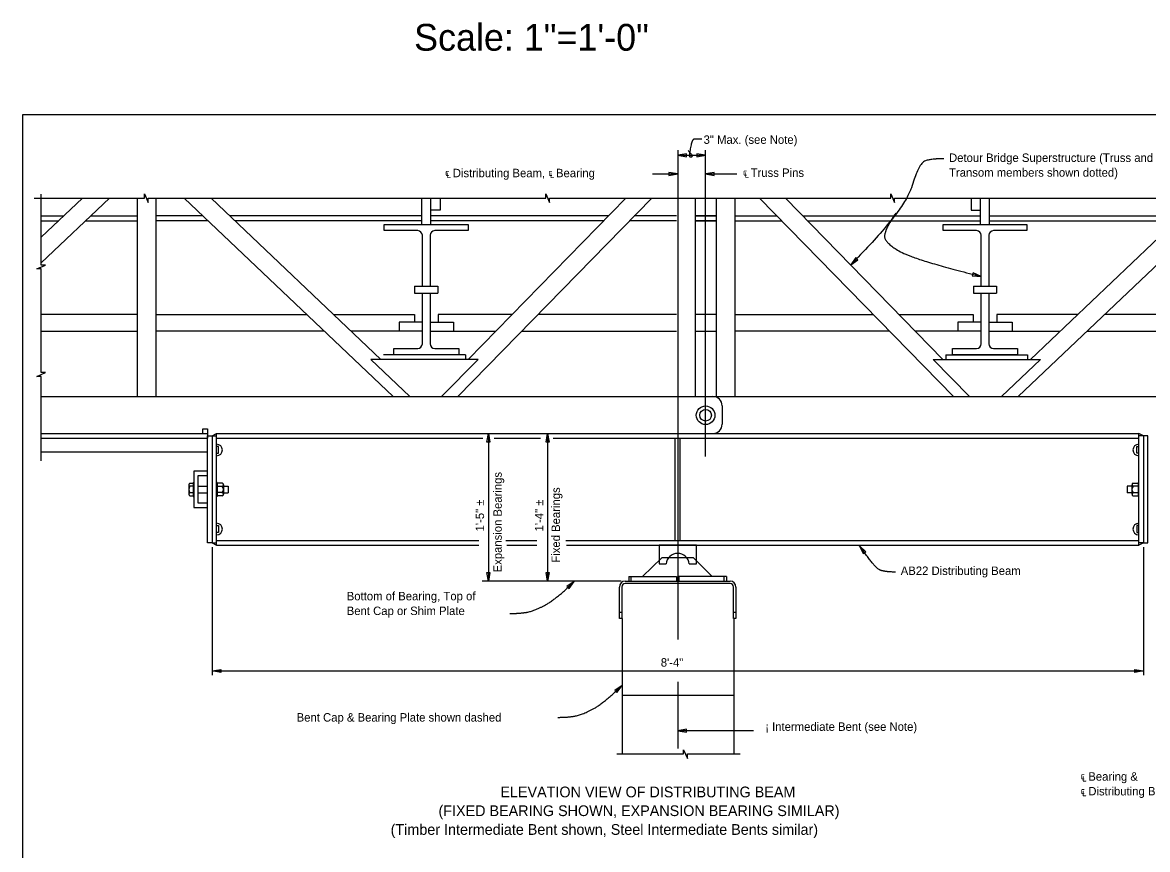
# Model space of a CAD drawing. Extents: x 112363.6 to 112390.2, y 109543.2 to 109558.
# Drawn here: x 112363.65 to 112373.71, y 109550.57 to 109557.97 of the extents above; entities that cross this region are included whole.
import ezdxf

# ---------------------------------------------------------------- set-up
doc = ezdxf.new("R2010")
doc.units = 0
for name, color, linetype in [('ActivePts-ConstElements', 7, 'Continuous'), ('CL_Minor', 7, 'Continuous'), ('Dimension', 7, 'Continuous'), ('SteelMisc', 7, 'Continuous'), ('SteelMisc_h', 7, 'Continuous'), ('Symbols', 7, 'Continuous'), ('TextStructures', 7, 'Continuous'), ('Wood', 7, 'Continuous')]:
    doc.layers.add(name, color=color, linetype=linetype)

msp = doc.modelspace()

# ---------------------------------------------------------------- linework, layer by layer
at = {"layer": 'ActivePts-ConstElements'}
msp.add_lwpolyline([(112363.648, 109547.417), (112379.042, 109547.417), (112379.042, 109557.147), (112363.648, 109557.147)], close=True, dxfattribs=at)
at = {"layer": 'CL_Minor'}
for p, q in [((112369.51, 109556.831), (112369.51, 109552.449)), ((112369.76, 109554.089), (112369.76, 109556.831)), ((112369.51, 109552.072), (112369.51, 109551.473))]:
    msp.add_line(p, q, dxfattribs=at)
at = {"layer": 'Dimension'}
for p, q in [((112369.51, 109556.786), (112369.76, 109556.786)), ((112369.284, 109556.619), (112369.51, 109556.619)), ((112369.76, 109556.619), (112370.04, 109556.619)), ((112367.816, 109554.294), (112367.816, 109552.972)), ((112368.346, 109554.294), (112368.346, 109552.972)), ((112365.344, 109553.278), (112365.344, 109552.131)), ((112373.677, 109553.278), (112373.677, 109552.131)), ((112369.004, 109552.972), (112367.76, 109552.972)), ((112365.344, 109552.169), (112373.677, 109552.169))]:
    msp.add_line(p, q, dxfattribs=at)
for points in [[(112369.51, 109556.786), (112369.588, 109556.773), (112369.588, 109556.799)], [(112369.76, 109556.786), (112369.682, 109556.799), (112369.682, 109556.773)], [(112369.51, 109556.619), (112369.432, 109556.632), (112369.432, 109556.605)], [(112369.76, 109556.619), (112369.838, 109556.605), (112369.838, 109556.632)], [(112371.058, 109555.804), (112371.122, 109555.85), (112371.103, 109555.869)], [(112372.225, 109555.701), (112372.153, 109555.732), (112372.146, 109555.707)], [(112367.803, 109554.216), (112367.816, 109554.294), (112367.829, 109554.216)], [(112368.333, 109554.216), (112368.346, 109554.294), (112368.359, 109554.216)], [(112371.137, 109553.29), (112371.171, 109553.219), (112371.193, 109553.234)], [(112367.829, 109553.05), (112367.816, 109552.972), (112367.803, 109553.05)], [(112368.359, 109553.05), (112368.346, 109552.972), (112368.333, 109553.05)], [(112368.584, 109552.97), (112368.519, 109552.924), (112368.538, 109552.906)], [(112365.422, 109552.156), (112365.344, 109552.169), (112365.422, 109552.182)], [(112373.599, 109552.182), (112373.677, 109552.169), (112373.599, 109552.156)], [(112369.012, 109552.039), (112368.947, 109551.994), (112368.966, 109551.975)], [(112369.51, 109551.633), (112369.588, 109551.62), (112369.588, 109551.646)]]:
    msp.add_lwpolyline(points, close=True, dxfattribs=at)
for points in [[(112369.726, 109556.93), (112369.673, 109556.93), (112369.648, 109556.93), (112369.631, 109556.892), (112369.614, 109556.791), (112369.614, 109556.772), (112369.642, 109556.772), (112369.642, 109556.789), (112369.604, 109556.828)], [(112371.89, 109556.755), (112371.797, 109556.755), (112371.667, 109556.721), (112371.547, 109556.301), (112371.058, 109555.804)], [(112371.461, 109556.268), (112371.361, 109556.118), (112371.361, 109556.002), (112371.635, 109555.848), (112372.225, 109555.701)], [(112371.459, 109553.054), (112371.347, 109553.054), (112371.269, 109553.103), (112371.137, 109553.29)], [(112368.009, 109552.683), (112368.101, 109552.683), (112368.226, 109552.706), (112368.422, 109552.81), (112368.584, 109552.97)], [(112368.437, 109551.753), (112368.529, 109551.753), (112368.654, 109551.776), (112368.85, 109551.879), (112369.012, 109552.039)]]:
    msp.add_open_spline(points, degree=2, dxfattribs=at)
at = {"layer": 'SteelMisc'}
for p, q in [((112364.427, 109556.403), (112363.815, 109555.822)), ((112364.185, 109556.403), (112363.815, 109556.052)), ((112364.677, 109554.625), (112364.677, 109556.403)), ((112364.844, 109554.625), (112364.844, 109556.403)), ((112365.093, 109556.403), (112366.964, 109554.625)), ((112365.335, 109556.403), (112366.855, 109554.958)), ((112367.22, 109556.167), (112367.22, 109556.403)), ((112367.301, 109556.167), (112367.301, 109556.403)), ((112367.544, 109554.625), (112369.279, 109556.403)), ((112367.636, 109554.958), (112369.046, 109556.403)), ((112369.666, 109556.403), (112369.666, 109554.625)), ((112369.854, 109556.403), (112369.854, 109554.625)), ((112370.021, 109556.403), (112370.021, 109554.625)), ((112371.977, 109554.625), (112370.242, 109556.403)), ((112371.884, 109554.958), (112370.474, 109556.403)), ((112372.22, 109556.167), (112372.22, 109556.403)), ((112372.301, 109556.167), (112372.301, 109556.403)), ((112374.428, 109556.403), (112372.557, 109554.625)), ((112374.186, 109556.403), (112372.666, 109554.958)), ((112363.815, 109556.242), (112364.016, 109556.242)), ((112363.815, 109556.2), (112363.972, 109556.2)), ((112364.214, 109556.2), (112364.677, 109556.2)), ((112364.258, 109556.242), (112364.677, 109556.242)), ((112365.262, 109556.242), (112364.844, 109556.242)), ((112365.306, 109556.2), (112364.844, 109556.2)), ((112367.22, 109556.242), (112365.504, 109556.242)), ((112367.22, 109556.2), (112365.548, 109556.2)), ((112366.885, 109556.111), (112366.885, 109556.167)), ((112366.885, 109556.167), (112367.635, 109556.167)), ((112368.889, 109556.242), (112367.301, 109556.242)), ((112368.849, 109556.2), (112367.301, 109556.2)), ((112367.635, 109556.167), (112367.635, 109556.111)), ((112369.5, 109556.2), (112369.082, 109556.2)), ((112369.5, 109556.242), (112369.122, 109556.242)), ((112369.854, 109556.242), (112369.666, 109556.242)), ((112369.666, 109556.242), (112369.854, 109556.242)), ((112369.666, 109556.2), (112369.854, 109556.2)), ((112369.854, 109556.2), (112369.666, 109556.2)), ((112370.021, 109556.242), (112370.398, 109556.242)), ((112370.021, 109556.2), (112370.439, 109556.2)), ((112370.631, 109556.242), (112372.22, 109556.242)), ((112370.672, 109556.2), (112372.22, 109556.2)), ((112371.885, 109556.111), (112371.885, 109556.167)), ((112371.885, 109556.167), (112372.635, 109556.167)), ((112372.301, 109556.242), (112374.017, 109556.242)), ((112372.301, 109556.2), (112373.973, 109556.2)), ((112372.635, 109556.167), (112372.635, 109556.111)), ((112367.184, 109556.111), (112366.885, 109556.111)), ((112367.226, 109555.615), (112367.226, 109556.069)), ((112367.295, 109556.069), (112367.295, 109555.615)), ((112367.635, 109556.111), (112367.336, 109556.111)), ((112372.184, 109556.111), (112371.885, 109556.111)), ((112372.226, 109555.615), (112372.226, 109556.069)), ((112372.294, 109556.069), (112372.294, 109555.615)), ((112372.635, 109556.111), (112372.336, 109556.111)), ((112367.156, 109555.615), (112367.156, 109555.552)), ((112367.156, 109555.615), (112367.365, 109555.615)), ((112367.365, 109555.615), (112367.365, 109555.552)), ((112372.156, 109555.615), (112372.156, 109555.552)), ((112372.156, 109555.615), (112372.364, 109555.615)), ((112372.364, 109555.615), (112372.364, 109555.552)), ((112367.156, 109555.552), (112367.365, 109555.552)), ((112367.226, 109555.098), (112367.226, 109555.552)), ((112367.295, 109555.552), (112367.295, 109555.098)), ((112372.156, 109555.552), (112372.364, 109555.552)), ((112372.226, 109555.098), (112372.226, 109555.552)), ((112372.294, 109555.552), (112372.294, 109555.098)), ((112367.154, 109555.361), (112367.154, 109555.292)), ((112367.367, 109555.361), (112367.367, 109555.292)), ((112372.154, 109555.361), (112372.154, 109555.292)), ((112372.366, 109555.361), (112372.366, 109555.292)), ((112367.018, 109555.292), (112367.018, 109555.211)), ((112367.226, 109555.292), (112367.018, 109555.292)), ((112367.295, 109555.292), (112367.503, 109555.292)), ((112367.503, 109555.292), (112367.503, 109555.211)), ((112372.018, 109555.292), (112372.018, 109555.211)), ((112372.226, 109555.292), (112372.018, 109555.292)), ((112372.294, 109555.292), (112372.503, 109555.292)), ((112372.503, 109555.292), (112372.503, 109555.211)), ((112366.969, 109555), (112366.969, 109555.056)), ((112366.969, 109555.056), (112367.184, 109555.056)), ((112367.336, 109555.056), (112367.552, 109555.056)), ((112367.552, 109555.056), (112367.552, 109555)), ((112371.968, 109555), (112371.968, 109555.056)), ((112371.968, 109555.056), (112372.184, 109555.056)), ((112372.336, 109555.056), (112372.552, 109555.056)), ((112372.552, 109555.056), (112372.552, 109555)), ((112367.724, 109554.958), (112366.764, 109554.958)), ((112366.764, 109554.958), (112367.115, 109554.625)), ((112367.612, 109555), (112366.879, 109555)), ((112367.398, 109554.625), (112367.724, 109554.958)), ((112367.612, 109555), (112367.612, 109554.96)), ((112372.122, 109554.625), (112371.797, 109554.958)), ((112371.797, 109554.958), (112372.756, 109554.958)), ((112371.909, 109555), (112372.641, 109555)), ((112371.909, 109555), (112371.909, 109554.96)), ((112372.756, 109554.958), (112372.406, 109554.625)), ((112372.641, 109555), (112372.641, 109554.957)), ((112363.815, 109554.625), (112378.284, 109554.625)), ((112369.908, 109554.542), (112369.908, 109554.378)), ((112363.815, 109554.294), (112365.303, 109554.294)), ((112365.344, 109554.274), (112365.385, 109554.294)), ((112365.344, 109554.274), (112365.385, 109554.274)), ((112365.385, 109553.294), (112365.385, 109554.294)), ((112365.385, 109554.294), (112373.635, 109554.294)), ((112365.385, 109554.254), (112367.767, 109554.254)), ((112367.867, 109554.254), (112368.284, 109554.254)), ((112368.397, 109554.254), (112373.635, 109554.254)), ((112369.489, 109553.335), (112369.489, 109554.254)), ((112369.531, 109553.335), (112369.531, 109554.254)), ((112373.635, 109553.294), (112373.635, 109554.294)), ((112373.677, 109554.274), (112373.635, 109554.294)), ((112373.677, 109554.274), (112373.635, 109554.274)), ((112365.403, 109554.178), (112365.385, 109554.178)), ((112365.403, 109554.117), (112365.403, 109554.178)), ((112373.617, 109554.117), (112373.617, 109554.178)), ((112373.617, 109554.178), (112373.635, 109554.178)), ((112363.815, 109554.13), (112365.303, 109554.13)), ((112365.385, 109554.117), (112365.403, 109554.117)), ((112373.635, 109554.117), (112373.617, 109554.117)), ((112365.146, 109553.85), (112365.175, 109553.85)), ((112365.175, 109553.856), (112365.18, 109553.856)), ((112365.175, 109553.856), (112365.175, 109553.731)), ((112365.391, 109553.856), (112365.385, 109553.856)), ((112365.391, 109553.856), (112365.391, 109553.731)), ((112365.435, 109553.85), (112365.391, 109553.85)), ((112373.585, 109553.85), (112373.63, 109553.85)), ((112373.63, 109553.856), (112373.635, 109553.856)), ((112373.63, 109553.856), (112373.63, 109553.731)), ((112365.135, 109553.835), (112365.135, 109553.751)), ((112365.175, 109553.822), (112365.146, 109553.822)), ((112365.146, 109553.765), (112365.175, 109553.765)), ((112365.221, 109553.824), (112365.303, 109553.824)), ((112365.221, 109553.762), (112365.303, 109553.762)), ((112365.391, 109553.822), (112365.435, 109553.822)), ((112365.435, 109553.765), (112365.391, 109553.765)), ((112365.446, 109553.835), (112365.446, 109553.751)), ((112365.446, 109553.824), (112365.488, 109553.824)), ((112365.446, 109553.762), (112365.488, 109553.762)), ((112365.488, 109553.824), (112365.488, 109553.762)), ((112373.575, 109553.824), (112373.533, 109553.824)), ((112373.533, 109553.824), (112373.533, 109553.762)), ((112373.575, 109553.762), (112373.533, 109553.762)), ((112373.575, 109553.835), (112373.575, 109553.751)), ((112373.63, 109553.822), (112373.585, 109553.822)), ((112373.585, 109553.765), (112373.63, 109553.765)), ((112365.146, 109553.736), (112365.175, 109553.736)), ((112365.175, 109553.731), (112365.18, 109553.731)), ((112365.391, 109553.731), (112365.385, 109553.731)), ((112365.435, 109553.736), (112365.391, 109553.736)), ((112373.585, 109553.736), (112373.63, 109553.736)), ((112373.63, 109553.731), (112373.635, 109553.731)), ((112365.385, 109553.47), (112365.403, 109553.47)), ((112365.403, 109553.47), (112365.403, 109553.408)), ((112373.617, 109553.47), (112373.617, 109553.408)), ((112373.635, 109553.47), (112373.617, 109553.47)), ((112365.403, 109553.408), (112365.385, 109553.408)), ((112365.403, 109553.408), (112365.385, 109553.408)), ((112373.617, 109553.408), (112373.635, 109553.408)), ((112365.344, 109553.315), (112365.385, 109553.315)), ((112365.344, 109553.315), (112365.385, 109553.294)), ((112365.385, 109553.335), (112367.732, 109553.335)), ((112365.385, 109553.294), (112367.732, 109553.294)), ((112367.974, 109553.335), (112368.249, 109553.335)), ((112367.982, 109553.294), (112368.249, 109553.294)), ((112368.51, 109553.335), (112373.635, 109553.335)), ((112368.514, 109553.294), (112373.635, 109553.294)), ((112373.677, 109553.315), (112373.635, 109553.315)), ((112373.677, 109553.315), (112373.635, 109553.294)), ((112369.367, 109553.18), (112369.195, 109553.013)), ((112369.653, 109553.18), (112369.367, 109553.18)), ((112369.653, 109553.18), (112369.82, 109553.013)), ((112369.041, 109552.972), (112369.979, 109552.972)), ((112369.979, 109552.951), (112369.041, 109552.951)), ((112369.073, 109553.013), (112369.073, 109552.972)), ((112369.073, 109553.013), (112369.5, 109553.013)), ((112369.094, 109552.972), (112369.094, 109553.013)), ((112369.5, 109553.013), (112369.5, 109552.972)), ((112369.948, 109553.013), (112369.521, 109553.013)), ((112369.521, 109553.013), (112369.521, 109552.972)), ((112369.927, 109552.972), (112369.927, 109553.013)), ((112369.948, 109553.013), (112369.948, 109552.972)), ((112368.989, 109552.638), (112368.989, 109552.92)), ((112369.01, 109552.92), (112369.01, 109552.638)), ((112370.01, 109552.638), (112370.01, 109552.92)), ((112370.031, 109552.92), (112370.031, 109552.638)), ((112368.989, 109552.694), (112369.01, 109552.694)), ((112369.01, 109552.638), (112368.989, 109552.638)), ((112370.01, 109552.694), (112370.031, 109552.694)), ((112370.031, 109552.638), (112370.01, 109552.638))]:
    msp.add_line(p, q, dxfattribs=at)
for points in [[(112367.384, 109556.403), (112367.384, 109556.295), (112367.301, 109556.295), (112367.301, 109556.403)], [(112372.136, 109556.403), (112372.136, 109556.295), (112372.22, 109556.295), (112372.22, 109556.403)], [(112364.677, 109555.361), (112363.815, 109555.361)], [(112364.844, 109555.361), (112366.192, 109555.361)], [(112366.434, 109555.361), (112367.154, 109555.361)], [(112368.029, 109555.361), (112367.367, 109555.361)], [(112369.5, 109555.361), (112368.262, 109555.361)], [(112369.854, 109555.361), (112369.666, 109555.361)], [(112370.021, 109555.361), (112371.258, 109555.361)], [(112371.491, 109555.361), (112372.154, 109555.361)], [(112373.089, 109555.361), (112372.366, 109555.361)], [(112374.677, 109555.361), (112373.331, 109555.361)], [(112363.815, 109555.211), (112364.677, 109555.211)], [(112366.35, 109555.211), (112364.844, 109555.211)], [(112367.226, 109555.211), (112366.592, 109555.211)], [(112367.295, 109555.211), (112367.883, 109555.211)], [(112368.116, 109555.211), (112369.5, 109555.211)], [(112369.666, 109555.211), (112369.854, 109555.211)], [(112371.405, 109555.211), (112370.021, 109555.211)], [(112372.226, 109555.211), (112371.638, 109555.211)], [(112372.294, 109555.211), (112372.931, 109555.211)], [(112373.173, 109555.211), (112374.677, 109555.211)], [(112367.552, 109555), (112367.26, 109555), (112366.969, 109555)], [(112372.552, 109555), (112372.26, 109555), (112371.968, 109555)], [(112365.262, 109554.294), (112365.262, 109554.336), (112365.303, 109554.336), (112365.303, 109554.254)], [(112369.614, 109553.128), (112369.677, 109553.128), (112369.677, 109553.294), (112369.344, 109553.294), (112369.344, 109553.128), (112369.407, 109553.128)]]:
    msp.add_lwpolyline(points, dxfattribs=at)
for points in [[(112365.344, 109553.315), (112365.303, 109553.315), (112365.303, 109554.274), (112365.344, 109554.274)], [(112373.677, 109553.315), (112373.718, 109553.315), (112373.718, 109554.274), (112373.677, 109554.274)], [(112365.303, 109553.958), (112365.18, 109553.958), (112365.18, 109553.631), (112365.303, 109553.631), (112365.303, 109553.672), (112365.221, 109553.672), (112365.221, 109553.917), (112365.303, 109553.917)]]:
    msp.add_lwpolyline(points, close=True, dxfattribs=at)
for radius in [0.0833, 0.0521]:
    msp.add_circle((112369.76, 109554.458), radius, dxfattribs=at)
for centre, radius, start, end in [((112367.184, 109556.069), 0.0417, 0, 90), ((112367.336, 109556.069), 0.0417, 90, 180), ((112372.184, 109556.069), 0.0417, 0, 90), ((112372.336, 109556.069), 0.0417, 90, 180), ((112367.184, 109555.098), 0.0417, 270, 0), ((112367.336, 109555.098), 0.0417, 180, 270), ((112372.184, 109555.098), 0.0417, 270, 0), ((112372.336, 109555.098), 0.0417, 180, 270), ((112369.825, 109554.542), 0.0833, 0, 90), ((112369.825, 109554.378), 0.0833, 270, 0), ((112365.385, 109554.147), 0.0514, 270.0279, 89.9721), ((112373.635, 109554.147), 0.0514, 90.0279, 269.9721), ((112365.15, 109553.836), 0.0149, 107.2558, 183.0154), ((112365.431, 109553.836), 0.0149, 356.9846, 72.7442), ((112373.59, 109553.836), 0.0149, 107.2558, 183.0154), ((112365.15, 109553.836), 0.0149, 183.0154, 252.7442), ((112365.18, 109553.793), 0.0441, 139.6401, 220.3599), ((112365.15, 109553.75), 0.0149, 107.2558, 176.9846), ((112365.15, 109553.75), 0.0149, 176.9846, 252.7442), ((112365.431, 109553.836), 0.0149, 287.2558, 356.9846), ((112365.402, 109553.793), 0.0441, 319.6401, 40.3599), ((112365.431, 109553.75), 0.0149, 3.0154, 72.7442), ((112365.431, 109553.75), 0.0149, 287.2558, 3.0154), ((112373.59, 109553.836), 0.0149, 183.0154, 252.7442), ((112373.619, 109553.793), 0.0441, 139.6401, 220.3599), ((112373.59, 109553.75), 0.0149, 107.2558, 176.9846), ((112373.59, 109553.75), 0.0149, 176.9846, 252.7442), ((112365.385, 109553.439), 0.0514, 270.0279, 89.9721), ((112373.635, 109553.439), 0.0514, 90.0279, 269.9721), ((112369.51, 109553.117), 0.104, 5.7032, 174.2968), ((112369.041, 109552.92), 0.052, 90, 180), ((112369.041, 109552.92), 0.0312, 90, 180), ((112369.979, 109552.92), 0.052, 0, 90), ((112369.979, 109552.92), 0.0312, 0, 90)]:
    msp.add_arc(centre, radius, start, end, dxfattribs=at)
at = {"layer": 'SteelMisc_h'}
msp.add_line((112363.815, 109554.254), (112365.303, 109554.254), dxfattribs=at)
at = {"layer": 'Symbols'}
for points in [[(112363.752, 109556.403), (112364.739, 109556.403), (112364.739, 109556.441), (112364.773, 109556.364), (112364.773, 109556.403), (112366.98, 109556.403)], [(112363.815, 109555.186), (112363.815, 109555.77), (112363.777, 109555.77), (112363.854, 109555.803), (112363.815, 109555.803), (112363.815, 109556.437)], [(112366.98, 109556.403), (112368.331, 109556.403), (112368.331, 109556.441), (112368.364, 109556.364), (112368.364, 109556.403), (112369.76, 109556.403)], [(112369.76, 109556.403), (112371.417, 109556.403), (112371.417, 109556.441), (112371.451, 109556.364), (112371.451, 109556.403), (112372.687, 109556.403)], [(112372.687, 109556.403), (112374.304, 109556.403), (112374.304, 109556.441), (112374.338, 109556.364), (112374.338, 109556.403), (112375.273, 109556.403)], [(112363.815, 109554.049), (112363.815, 109554.806), (112363.777, 109554.806), (112363.854, 109554.84), (112363.815, 109554.84), (112363.815, 109555.186)], [(112368.966, 109551.425), (112369.563, 109551.425), (112369.563, 109551.463), (112369.597, 109551.386), (112369.597, 109551.425), (112370.07, 109551.425)]]:
    msp.add_lwpolyline(points, dxfattribs=at)
at = {"layer": 'TextStructures'}
msp.add_line((112370.189, 109551.633), (112369.51, 109551.633), dxfattribs=at)
at = {"layer": 'Wood'}
for p, q in [((112369.012, 109552.638), (112369.012, 109551.425)), ((112370.012, 109552.638), (112370.012, 109551.425)), ((112369.011, 109551.951), (112370.01, 109551.951))]:
    msp.add_line(p, q, dxfattribs=at)

# ---------------------------------------------------------------- texts
at = {"layer": 'Dimension'}
for s, p in [('1\'-5" ±', (112367.778, 109553.418)), ('1\'-4" ±', (112368.308, 109553.418))]:
    msp.add_text(s, height=0.0756, rotation=90, dxfattribs=at).set_placement(p)
msp.add_text('8\'-4"', height=0.0756, dxfattribs=at).set_placement((112369.359, 109552.207))
at = {"layer": 'TextStructures'}
for s, height, p in [('Scale: 1"=1\'-0"', 0.24, (112367.152, 109557.722)), ('3" Max. (see Note)', 0.0756, (112369.742, 109556.888)), ('Detour Bridge Superstructure (Truss and ', 0.0756, (112371.938, 109556.726)), ('℄ Distributing Beam, ℄ Bearing', 0.0756, (112367.429, 109556.589)), ('℄ Truss Pins', 0.0756, (112370.094, 109556.592)), ('Transom members shown dotted)', 0.0756, (112371.938, 109556.594)), ('AB22 Distributing Beam', 0.0756, (112371.506, 109553.028)), ('Bottom of Bearing, Top of ', 0.0756, (112366.549, 109552.801)), ('Bent Cap or Shim Plate', 0.0756, (112366.549, 109552.669)), ('Bent Cap & Bearing Plate shown dashed', 0.0756, (112366.101, 109551.715)), ('¡ Intermediate Bent (see Note)', 0.0756, (112370.293, 109551.632)), ('℄ Bearing & ', 0.0756, (112373.115, 109551.186)), ('ELEVATION VIEW OF DISTRIBUTING BEAM', 0.096, (112367.924, 109551.037)), ('℄ Distributing Beam', 0.0756, (112373.115, 109551.054)), ('(FIXED BEARING SHOWN, EXPANSION BEARING SIMILAR)', 0.096, (112367.37, 109550.869)), ('(Timber Intermediate Bent shown, Steel Intermediate Bents similar) ', 0.096, (112366.942, 109550.701))]:
    msp.add_text(s, height=height, dxfattribs=at).set_placement(p)
for s, p in [('Expansion Bearings', (112367.936, 109553.051)), ('Fixed Bearings', (112368.457, 109553.138))]:
    msp.add_text(s, height=0.0756, rotation=90, dxfattribs=at).set_placement(p)

doc.saveas('drawing.dxf')
